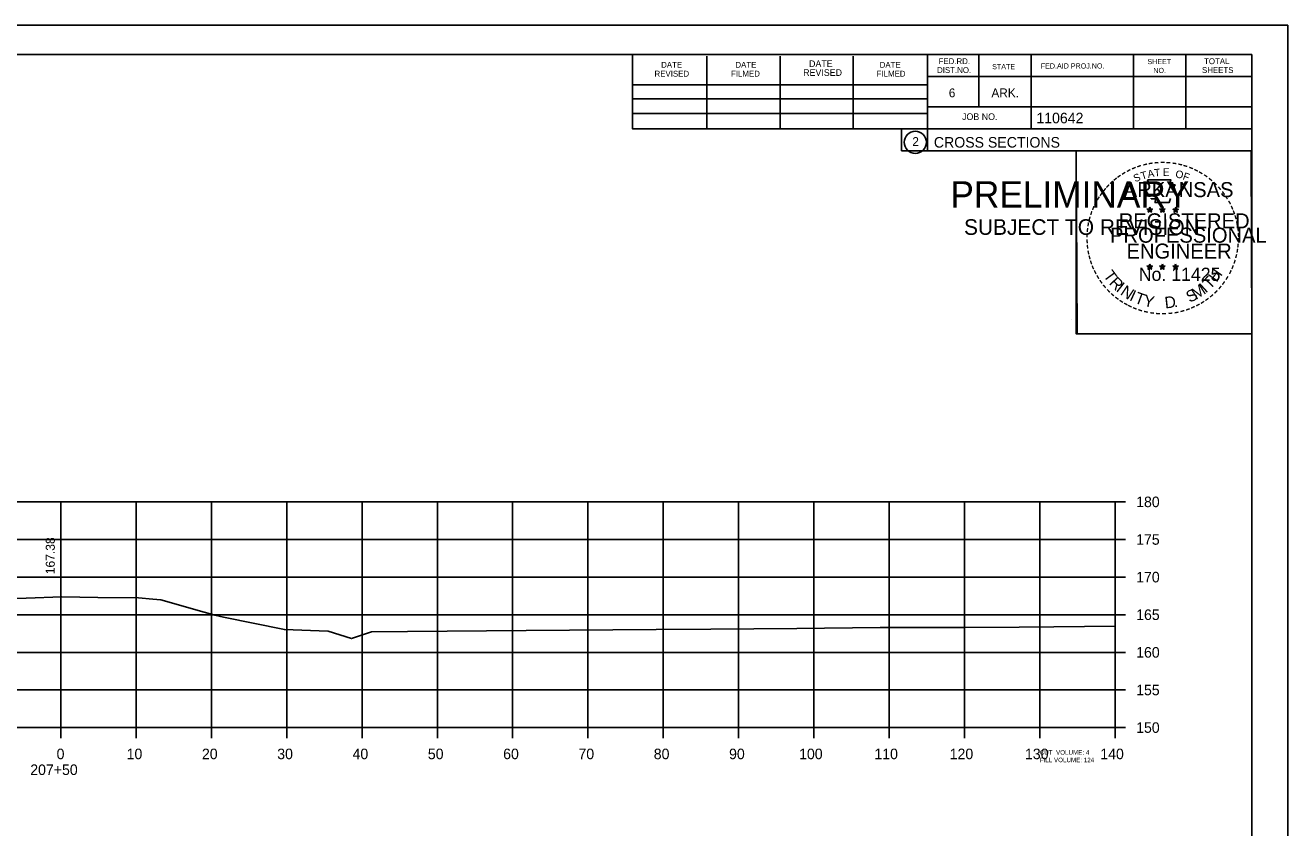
# Model space of a CAD drawing. Extents: x 1368503 to 1373085, y 379840 to 381833.
# Drawn here: x 1368668.3 to 1368836, y 380232.7 to 380339.4 of the extents above; entities that cross this region are included whole.
import ezdxf

# ---------------------------------------------------------------- set-up
doc = ezdxf.new("R2010")
doc.units = 0
for name, color, linetype in [('S_BRIDGE', 7, 'Continuous'), ('S_EDGE_PAVEMENT', 7, 'Continuous'), ('S_LANDSCAPING', 7, 'Continuous'), ('S_MISC_BOUNDARY', 7, 'Continuous'), ('S_MISC_BOUNDARY_ANNOT', 7, 'Continuous'), ('S_PHOTO_CENTERS', 7, 'Continuous'), ('S_PHOTO_NOTES', 7, 'Continuous'), ('S_TRAILS', 7, 'Continuous'), ('S_TRAILS_ANNOT', 7, 'Continuous')]:
    doc.layers.add(name, color=color, linetype=linetype)

msp = doc.modelspace()

# ---------------------------------------------------------------- linework, layer by layer
at = {"layer": 'S_BRIDGE'}
for p, q in [((1368515.06, 380335.49), (1368831.24, 380335.49)), ((1368748.98, 380325.61), (1368748.98, 380335.49)), ((1368758.84, 380325.61), (1368758.84, 380335.29)), ((1368768.6, 380325.61), (1368768.6, 380335.29)), ((1368778.28, 380325.61), (1368778.28, 380335.29)), ((1368788.14, 380335.49), (1368788.14, 380322.69)), ((1368794.98, 380335.49), (1368794.98, 380328.55)), ((1368801.92, 380335.49), (1368801.92, 380325.61)), ((1368815.5, 380335.49), (1368815.5, 380325.61)), ((1368822.44, 380335.49), (1368822.44, 380325.61)), ((1368831.24, 380130.03), (1368831.24, 380335.49)), ((1368748.98, 380331.47), (1368788.14, 380331.47)), ((1368831.24, 380332.55), (1368788.14, 380332.55)), ((1368831.24, 380332.57), (1368831.24, 380332.57)), ((1368748.98, 380329.61), (1368788.14, 380329.61)), ((1368831.24, 380328.55), (1368788.14, 380328.55)), ((1368791.1, 380328.55), (1368831.24, 380328.55)), ((1368748.98, 380325.61), (1368748.98, 380327.67)), ((1368748.98, 380327.67), (1368788.14, 380327.67)), ((1368831.24, 380325.61), (1368748.98, 380325.61)), ((1368788.14, 380322.69), (1368831.24, 380322.69))]:
    msp.add_line(p, q, dxfattribs=at)
msp.add_circle((1368786.53, 380323.82), 1.47, dxfattribs=at)
at = {"layer": 'S_EDGE_PAVEMENT'}
for p, q in [((1368813.06, 380246.03), (1368813.06, 380276.03)), ((1368814.46, 380276.03), (1368813.06, 380276.03)), ((1368814.46, 380271.03), (1368813.06, 380271.03)), ((1368814.46, 380266.03), (1368813.06, 380266.03)), ((1368814.46, 380261.03), (1368813.06, 380261.03)), ((1368814.46, 380256.03), (1368813.06, 380256.03)), ((1368814.46, 380251.03), (1368813.06, 380251.03)), ((1368533.06, 380246.03), (1368813.06, 380246.03)), ((1368673.06, 380244.63), (1368673.06, 380246.03)), ((1368683.06, 380244.63), (1368683.06, 380246.03)), ((1368693.06, 380244.63), (1368693.06, 380246.03)), ((1368703.06, 380244.63), (1368703.06, 380246.03)), ((1368713.06, 380244.63), (1368713.06, 380246.03)), ((1368723.06, 380244.63), (1368723.06, 380246.03)), ((1368733.06, 380244.63), (1368733.06, 380246.03)), ((1368743.06, 380244.63), (1368743.06, 380246.03)), ((1368753.06, 380244.63), (1368753.06, 380246.03)), ((1368763.06, 380244.63), (1368763.06, 380246.03)), ((1368773.06, 380244.63), (1368773.06, 380246.03)), ((1368783.06, 380244.63), (1368783.06, 380246.03)), ((1368793.06, 380244.63), (1368793.06, 380246.03)), ((1368803.06, 380244.63), (1368803.06, 380246.03)), ((1368813.06, 380244.63), (1368813.06, 380246.03)), ((1368814.46, 380246.03), (1368813.06, 380246.03))]:
    msp.add_line(p, q, dxfattribs=at)
at = {"layer": 'S_LANDSCAPING'}
for p, q in [((1368817.32, 380314.94), (1368817.67, 380314.83)), ((1368817.32, 380314.94), (1368817.58, 380314.9)), ((1368817.32, 380314.94), (1368817.56, 380314.82)), ((1368817.46, 380314.54), (1368817.67, 380314.83)), ((1368817.46, 380314.54), (1368817.58, 380314.78)), ((1368817.46, 380314.54), (1368817.67, 380314.75)), ((1368817.67, 380315.2), (1368817.63, 380314.95)), ((1368817.67, 380314.83), (1368817.67, 380315.2)), ((1368817.67, 380315.2), (1368817.72, 380314.95)), ((1368818.02, 380314.94), (1368817.67, 380314.83)), ((1368817.89, 380314.54), (1368817.67, 380314.83)), ((1368817.89, 380314.54), (1368817.67, 380314.75)), ((1368818.02, 380314.94), (1368817.73, 380314.89)), ((1368817.89, 380314.54), (1368817.75, 380314.83)), ((1368818.02, 380314.94), (1368817.82, 380314.84)), ((1368818.99, 380314.94), (1368819.34, 380314.83)), ((1368818.99, 380314.94), (1368819.25, 380314.9)), ((1368818.99, 380314.94), (1368819.23, 380314.82)), ((1368819.13, 380314.54), (1368819.34, 380314.83)), ((1368819.13, 380314.54), (1368819.25, 380314.78)), ((1368819.13, 380314.54), (1368819.34, 380314.75)), ((1368819.34, 380315.2), (1368819.3, 380314.95)), ((1368819.34, 380314.83), (1368819.34, 380315.2)), ((1368819.34, 380315.2), (1368819.39, 380314.95)), ((1368819.69, 380314.94), (1368819.34, 380314.83)), ((1368819.56, 380314.54), (1368819.34, 380314.83)), ((1368819.56, 380314.54), (1368819.34, 380314.75)), ((1368819.69, 380314.94), (1368819.4, 380314.89)), ((1368819.56, 380314.54), (1368819.42, 380314.83)), ((1368819.69, 380314.94), (1368819.49, 380314.84)), ((1368820.76, 380314.93), (1368821.11, 380314.82)), ((1368820.76, 380314.93), (1368821.01, 380314.89)), ((1368820.76, 380314.93), (1368820.99, 380314.81)), ((1368820.89, 380314.52), (1368821.11, 380314.82)), ((1368820.89, 380314.52), (1368821.02, 380314.77)), ((1368820.89, 380314.52), (1368821.1, 380314.74)), ((1368821.11, 380315.19), (1368821.07, 380314.93)), ((1368821.32, 380314.52), (1368821.1, 380314.74)), ((1368821.11, 380314.82), (1368821.11, 380315.19)), ((1368821.11, 380315.19), (1368821.16, 380314.94)), ((1368821.45, 380314.93), (1368821.11, 380314.82)), ((1368821.32, 380314.52), (1368821.11, 380314.82)), ((1368821.45, 380314.93), (1368821.17, 380314.88)), ((1368821.32, 380314.52), (1368821.18, 380314.81)), ((1368821.45, 380314.93), (1368821.25, 380314.83)), ((1368817.32, 380307.37), (1368817.67, 380307.26)), ((1368817.32, 380307.37), (1368817.57, 380307.33)), ((1368817.32, 380307.37), (1368817.56, 380307.25)), ((1368817.45, 380306.96), (1368817.67, 380307.26)), ((1368817.45, 380306.96), (1368817.58, 380307.21)), ((1368817.45, 380306.96), (1368817.67, 380307.18)), ((1368817.67, 380307.62), (1368817.63, 380307.37)), ((1368817.67, 380307.26), (1368817.67, 380307.62)), ((1368817.67, 380307.62), (1368817.72, 380307.37)), ((1368818.02, 380307.37), (1368817.67, 380307.26)), ((1368817.88, 380306.96), (1368817.67, 380307.26)), ((1368817.88, 380306.96), (1368817.67, 380307.18)), ((1368818.02, 380307.37), (1368817.73, 380307.32)), ((1368817.88, 380306.96), (1368817.74, 380307.25)), ((1368818.02, 380307.37), (1368817.81, 380307.27)), ((1368818.99, 380307.37), (1368819.34, 380307.26)), ((1368818.99, 380307.37), (1368819.24, 380307.33)), ((1368818.99, 380307.37), (1368819.23, 380307.25)), ((1368819.12, 380306.96), (1368819.34, 380307.26)), ((1368819.12, 380306.96), (1368819.25, 380307.21)), ((1368819.12, 380306.96), (1368819.34, 380307.18)), ((1368819.34, 380307.62), (1368819.3, 380307.37)), ((1368819.34, 380307.26), (1368819.34, 380307.62)), ((1368819.34, 380307.62), (1368819.39, 380307.37)), ((1368819.68, 380307.37), (1368819.34, 380307.26)), ((1368819.55, 380306.96), (1368819.34, 380307.26)), ((1368819.55, 380306.96), (1368819.34, 380307.18)), ((1368819.68, 380307.37), (1368819.4, 380307.32)), ((1368819.55, 380306.96), (1368819.41, 380307.25)), ((1368819.68, 380307.37), (1368819.48, 380307.27)), ((1368820.76, 380307.36), (1368821.1, 380307.25)), ((1368820.76, 380307.36), (1368821.01, 380307.32)), ((1368820.76, 380307.36), (1368820.99, 380307.24)), ((1368820.89, 380306.95), (1368821.1, 380307.25)), ((1368820.89, 380306.95), (1368821.01, 380307.2)), ((1368820.89, 380306.95), (1368821.1, 380307.17)), ((1368821.1, 380307.61), (1368821.06, 380307.36)), ((1368821.1, 380307.25), (1368821.1, 380307.61)), ((1368821.1, 380307.61), (1368821.15, 380307.36)), ((1368821.45, 380307.36), (1368821.1, 380307.25)), ((1368821.32, 380306.95), (1368821.1, 380307.25)), ((1368821.32, 380306.95), (1368821.1, 380307.17)), ((1368821.45, 380307.36), (1368821.17, 380307.31)), ((1368821.32, 380306.95), (1368821.18, 380307.24)), ((1368821.45, 380307.36), (1368821.25, 380307.26))]:
    msp.add_line(p, q, dxfattribs=at)
for points in [[(1368817.36, 380318.82), (1368817.63, 380317.99)], [(1368820.88, 380317.9), (1368821.02, 380318.18), (1368820.33, 380318.16), (1368820.48, 380318.82), (1368817.36, 380318.82)], [(1368817.86, 380316.4), (1368817.86, 380316.31), (1368818.42, 380316.29), (1368818.37, 380315.82), (1368820.24, 380315.82), (1368820.44, 380316.36)], [(1368817.67, 380315.2), (1368817.89, 380314.54), (1368817.32, 380314.94), (1368818.02, 380314.94), (1368817.46, 380314.54), (1368817.67, 380315.2)], [(1368819.34, 380315.2), (1368819.56, 380314.54), (1368818.99, 380314.94), (1368819.69, 380314.94), (1368819.13, 380314.54), (1368819.34, 380315.2)], [(1368821.11, 380315.19), (1368821.32, 380314.52), (1368820.76, 380314.93), (1368821.45, 380314.93), (1368820.89, 380314.52), (1368821.11, 380315.19)], [(1368817.67, 380307.62), (1368817.88, 380306.96), (1368817.32, 380307.37), (1368818.02, 380307.37), (1368817.45, 380306.96), (1368817.67, 380307.62)], [(1368819.34, 380307.62), (1368819.55, 380306.96), (1368818.99, 380307.37), (1368819.68, 380307.37), (1368819.12, 380306.96), (1368819.34, 380307.62)], [(1368821.1, 380307.61), (1368821.32, 380306.95), (1368820.76, 380307.36), (1368821.45, 380307.36), (1368820.89, 380306.95), (1368821.1, 380307.61)]]:
    msp.add_lwpolyline(points, dxfattribs=at)
for centre, radius in [((1368817.67, 380314.83), 0.172), ((1368817.67, 380314.83), 0.145), ((1368817.67, 380314.83), 0.116), ((1368817.67, 380314.83), 0.0991), ((1368817.67, 380314.83), 0.0747), ((1368817.67, 380314.83), 0.0495), ((1368817.67, 380314.83), 0.0296), ((1368819.34, 380314.83), 0.172), ((1368819.34, 380314.83), 0.145), ((1368819.34, 380314.83), 0.116), ((1368819.34, 380314.83), 0.0991), ((1368819.34, 380314.83), 0.0747), ((1368819.34, 380314.83), 0.0495), ((1368819.34, 380314.83), 0.0296), ((1368821.11, 380314.82), 0.172), ((1368821.11, 380314.82), 0.145), ((1368821.11, 380314.82), 0.116), ((1368821.11, 380314.82), 0.0991), ((1368821.11, 380314.82), 0.0747), ((1368821.11, 380314.82), 0.0495), ((1368821.11, 380314.82), 0.0296), ((1368817.67, 380307.26), 0.172), ((1368817.67, 380307.26), 0.145), ((1368817.67, 380307.26), 0.116), ((1368817.67, 380307.26), 0.0991), ((1368817.67, 380307.26), 0.0747), ((1368817.67, 380307.26), 0.0495), ((1368817.67, 380307.26), 0.0296), ((1368819.34, 380307.26), 0.172), ((1368819.34, 380307.26), 0.145), ((1368819.34, 380307.26), 0.116), ((1368819.34, 380307.26), 0.0991), ((1368819.34, 380307.26), 0.0747), ((1368819.34, 380307.26), 0.0495), ((1368819.34, 380307.26), 0.0296), ((1368821.1, 380307.25), 0.172), ((1368821.1, 380307.25), 0.145), ((1368821.1, 380307.25), 0.116), ((1368821.1, 380307.25), 0.0991), ((1368821.1, 380307.25), 0.0747), ((1368821.1, 380307.25), 0.0495), ((1368821.1, 380307.25), 0.0296)]:
    msp.add_circle(centre, radius, dxfattribs=at)
at = {"layer": 'S_MISC_BOUNDARY'}
msp.add_lwpolyline([(1368663, 380263.05), (1368668.44, 380263.25), (1368673.18, 380263.41), (1368677.97, 380263.33), (1368683.39, 380263.26), (1368685.3, 380263.1), (1368686.35, 380263.01), (1368692.08, 380261.39), (1368693.52, 380260.96), (1368694.68, 380260.7), (1368702.75, 380259.06), (1368708.52, 380258.86), (1368708.53, 380258.86), (1368708.54, 380258.86), (1368711.66, 380257.87), (1368713.77, 380258.56), (1368714.32, 380258.74), (1368719.09, 380258.79), (1368734.87, 380258.92), (1368752.13, 380259.08), (1368759.39, 380259.13), (1368770.78, 380259.22), (1368781.85, 380259.32), (1368786.11, 380259.32), (1368793.13, 380259.35), (1368800.34, 380259.39), (1368804.95, 380259.41), (1368813.06, 380259.49)], dxfattribs=at)
at = {"layer": 'S_PHOTO_CENTERS'}
for p, q in [((1368533.06, 380276.03), (1368813.06, 380276.03)), ((1368673.06, 380246.03), (1368673.06, 380276.03)), ((1368683.06, 380246.03), (1368683.06, 380276.03)), ((1368693.06, 380246.03), (1368693.06, 380276.03)), ((1368703.06, 380246.03), (1368703.06, 380276.03)), ((1368713.06, 380246.03), (1368713.06, 380276.03)), ((1368723.06, 380246.03), (1368723.06, 380276.03)), ((1368733.06, 380246.03), (1368733.06, 380276.03)), ((1368743.06, 380246.03), (1368743.06, 380276.03)), ((1368753.06, 380246.03), (1368753.06, 380276.03)), ((1368763.06, 380246.03), (1368763.06, 380276.03)), ((1368773.06, 380246.03), (1368773.06, 380276.03)), ((1368783.06, 380246.03), (1368783.06, 380276.03)), ((1368793.06, 380246.03), (1368793.06, 380276.03)), ((1368803.06, 380246.03), (1368803.06, 380276.03)), ((1368813.06, 380246.03), (1368813.06, 380276.03)), ((1368533.06, 380271.03), (1368813.06, 380271.03)), ((1368533.06, 380266.03), (1368813.06, 380266.03)), ((1368533.06, 380261.03), (1368813.06, 380261.03)), ((1368533.06, 380256.03), (1368813.06, 380256.03)), ((1368533.06, 380251.03), (1368813.06, 380251.03)), ((1368533.06, 380246.03), (1368813.06, 380246.03))]:
    msp.add_line(p, q, dxfattribs=at)
at = {"layer": 'S_PHOTO_NOTES'}
for p, q in [((1368502.66, 380339.38), (1368835.99, 380339.38)), ((1368807.27, 380300.23), (1368807.27, 380300.23))]:
    msp.add_line(p, q, dxfattribs=at)
for points in [[(1368502.65, 380339.38), (1368835.99, 380339.38), (1368835.99, 380126.05), (1368502.65, 380126.05)], [(1368748.98, 380335.49), (1368748.98, 380325.61), (1368784.71, 380325.61), (1368784.71, 380322.69), (1368807.91, 380322.69), (1368807.91, 380298.36), (1368831.24, 380298.36), (1368831.24, 380130.03), (1368515.06, 380130.03), (1368515.06, 380335.49)], [(1368807.91, 380322.69), (1368831.12, 380322.69), (1368831.24, 380298.36), (1368808.03, 380298.36)]]:
    msp.add_lwpolyline(points, close=True, dxfattribs=at)

# ---------------------------------------------------------------- texts
at = {"layer": 'S_BRIDGE'}
for s, height, p in [('DATE', 0.879, (1368772.42, 380333.83)), ('FED.RD.', 0.782, (1368789.62, 380334.21)), ('SHEET', 0.684, (1368817.36, 380334.21)), ('TOTAL', 0.782, (1368824.88, 380334.21)), ('REVISED', 0.782, (1368751.9, 380332.55)), ('DATE', 0.782, (1368752.78, 380333.73)), ('FILMED', 0.782, (1368762.06, 380332.55)), ('DATE', 0.782, (1368762.64, 380333.73)), ('REVISED', 0.879, (1368771.64, 380332.65)), ('FILMED', 0.782, (1368781.4, 380332.55)), ('DATE', 0.782, (1368781.8, 380333.73)), ('DIST.NO.', 0.782, (1368789.42, 380333.03)), ('STATE', 0.684, (1368796.74, 380333.53)), ('FED.AID PROJ.NO.', 0.684, (1368803.2, 380333.63)), ('NO.', 0.684, (1368818.14, 380333.03)), ('SHEETS', 0.782, (1368824.6, 380333.03)), ('6', 1.17, (1368790.98, 380329.81)), ('ARK.', 1.172, (1368796.64, 380329.81)), ('JOB NO.', 0.879, (1368792.74, 380326.79)), ('110642', 1.4, (1368802.61, 380326.35)), ('CROSS SECTIONS', 1.4, (1368789, 380323.12)), ('2', 1.17, (1368786.14, 380323.34))]:
    msp.add_text(s, height=height, rotation=360, dxfattribs=at).set_placement(p)
at = {"layer": 'S_LANDSCAPING'}
for s, height, rotation, p in [('-', 1.6, 5.8968, (1368818.27, 380320.46)), ('-', 1.6, 0.1862, (1368819.04, 380320.53)), ('-', 1.6, 357.743, (1368819.76, 380320.52)), ('-', 1.6, 36.2317, (1368813.67, 380318.6)), ('-', 1.6, 34.0636, (1368814.25, 380318.99)), ('-', 1.6, 28.7918, (1368814.85, 380319.36)), ('-', 1.6, 24.3072, (1368815.48, 380319.68)), ('S', 1, 21.594, (1368815.72, 380318.5)), ('-', 1.6, 19.1761, (1368816.11, 380319.95)), ('T', 1, 16.4036, (1368816.63, 380318.83)), ('-', 1.6, 13.6301, (1368816.86, 380320.19)), ('A', 1, 11.2132, (1368817.46, 380319.08)), ('-', 1.6, 10.2193, (1368817.54, 380320.35)), ('T', 1, 6.0228, (1368818.31, 380319.25)), ('E', 1, 0.8323, (1368819.41, 380319.36)), ('-', 1.6, 352.1617, (1368820.51, 380320.46)), ('O', 1, 350.4515, (1368821.02, 380319.15)), ('-', 1.6, 347.2049, (1368821.23, 380320.35)), ('F', 1, 340.0707, (1368821.97, 380318.92)), ('-', 1.6, 342.3362, (1368821.86, 380320.2)), ('-', 1.6, 337.8551, (1368822.6, 380319.97)), ('-', 1.6, 334.1211, (1368823.23, 380319.7)), ('-', 1.6, 329.6409, (1368823.81, 380319.42)), ('-', 1.6, 325.8627, (1368824.45, 380319.06)), ('-', 1.6, 48.423, (1368812.31, 380317.32)), ('-', 1.6, 42.9622, (1368812.76, 380317.8)), ('-', 1.6, 38.9507, (1368813.19, 380318.22)), ('ARKANSAS', 2, 360, (1368814.22, 380316.53)), ('-', 1.6, 320.5297, (1368825.06, 380318.63)), ('-', 1.6, 315.5786, (1368825.66, 380318.14)), ('-', 1.6, 309.8797, (1368826.23, 380317.59)), ('-', 1.6, 58.0706, (1368811.17, 380315.74)), ('-', 1.6, 54.2325, (1368811.5, 380316.27)), ('-', 1.6, 50.6142, (1368811.91, 380316.84)), ('-', 1.6, 306.6522, (1368826.75, 380316.99)), ('-', 1.4, 303.6753, (1368827.24, 380316.42)), ('-', 1.6, 72.3945, (1368810.38, 380313.89)), ('-', 1.6, 67.7743, (1368810.6, 380314.52)), ('-', 1.6, 62.8713, (1368810.86, 380315.13)), ('DWB', 0.01, 360, (1368817.66, 380314.83)), ('DWB', 0.01, 360, (1368819.33, 380314.83)), ('DWB', 0.01, 360, (1368821.09, 380314.82)), ('-', 1.6, 299.6684, (1368827.56, 380315.82)), ('-', 1.6, 294.6628, (1368827.88, 380315.2)), ('-', 1.6, 290.5728, (1368828.14, 380314.63)), ('-', 1.6, 81.2013, (1368810.05, 380312.46)), ('-', 1.6, 75.461, (1368810.18, 380313.18)), ('REGISTERED', 2, 360, (1368813.54, 380312.38)), ('-', 1.6, 285.1233, (1368828.37, 380314.05)), ('-', 1.6, 280.5493, (1368828.57, 380313.31)), ('-', 1.6, 89.0622, (1368809.95, 380311.07)), ('-', 1.6, 85.1863, (1368809.98, 380311.77)), ('PROFESSIONAL', 2, 360, (1368812.39, 380310.48)), ('-', 1.6, 276.5962, (1368828.74, 380312.54)), ('-', 1.6, 274.3301, (1368828.8, 380311.82)), ('-', 1.6, 94.1959, (1368809.99, 380310.35)), ('-', 1.6, 98.9479, (1368810.06, 380309.68)), ('ENGINEER', 2, 360, (1368814.58, 380308.36)), ('-', 1.6, 260.9953, (1368828.74, 380309.86)), ('-', 1.6, 263.5172, (1368828.81, 380310.52)), ('-', 1.6, 269.9407, (1368828.83, 380311.18)), ('-', 1.6, 101.7149, (1368810.19, 380308.95)), ('-', 1.6, 105.4578, (1368810.36, 380308.35)), ('-', 1.6, 109.0874, (1368810.57, 380307.72)), ('-', 1.6, 252.8681, (1368828.45, 380308.47)), ('-', 1.6, 255.7626, (1368828.63, 380309.19)), ('-', 1.6, 114.0643, (1368810.82, 380307.12)), ('-', 1.6, 115.7289, (1368811.13, 380306.51)), ('-', 1.6, 120.4471, (1368811.49, 380305.92)), ('T', 1.54, 306.0406, (1368811.43, 380306.1)), ('No. 11425', 1.757, 360, (1368816.21, 380305.4)), ('DWB', 0.01, 360, (1368817.66, 380307.25)), ('DWB', 0.01, 360, (1368819.33, 380307.25)), ('DWB', 0.01, 360, (1368821.09, 380307.24)), ('T', 1.54, 46.6444, (1368825.66, 380304.19)), ('H', 1.54, 54.6088, (1368826.55, 380305.13)), ('-', 1.6, 244.6197, (1368827.96, 380307.16)), ('-', 1.6, 247.8887, (1368828.23, 380307.79)), ('-', 1.6, 125.8934, (1368811.89, 380305.36)), ('-', 1.6, 130.7181, (1368812.35, 380304.81)), ('R', 1.54, 314.005, (1368812.19, 380305.05)), ('I', 1.54, 321.9694, (1368813.09, 380304.12)), ('N', 1.54, 326.5002, (1368813.66, 380303.65)), ('M', 1.54, 32.6563, (1368823.81, 380302.87)), ('I', 1.54, 42.1136, (1368825.1, 380303.71)), ('-', 1.6, 231.2538, (1368826.74, 380305.19)), ('-', 1.6, 233.8452, (1368827.17, 380305.76)), ('-', 1.6, 239.0712, (1368827.57, 380306.41)), ('-', 1.6, 134.2238, (1368812.87, 380304.26)), ('-', 1.6, 138.9338, (1368813.39, 380303.8)), ('-', 1.6, 144.6463, (1368813.95, 380303.39)), ('-', 1.6, 148.0898, (1368814.51, 380303.02)), ('I', 1.54, 335.3603, (1368814.87, 380302.86)), ('T', 1.54, 339.8912, (1368815.53, 380302.53)), ('Y', 1.54, 347.8556, (1368816.74, 380302.09)), ('D', 1.54, 6.3969, (1368819.73, 380301.73)), ('S', 1.54, 26.9312, (1368822.97, 380302.46)), ('-', 1.6, 212.2491, (1368824.65, 380303.26)), ('-', 1.6, 215.7363, (1368825.19, 380303.65)), ('-', 1.6, 221.0851, (1368825.74, 380304.12)), ('-', 1.6, 225.7653, (1368826.26, 380304.63)), ('-', 1.6, 151.5704, (1368815.09, 380302.7)), ('-', 1.6, 154.6002, (1368815.61, 380302.45)), ('-', 1.6, 158.5612, (1368816.24, 380302.19)), ('-', 1.6, 162.7983, (1368816.92, 380301.98)), ('-', 1.6, 167.5555, (1368817.64, 380301.82)), ('-', 1.6, 173.1155, (1368818.41, 380301.71)), ('-', 1.6, 176.5183, (1368819.16, 380301.65)), ('-', 1.6, 181.5918, (1368819.9, 380301.67)), ('-', 1.6, 185.8167, (1368820.71, 380301.75)), ('-', 1.6, 191.2858, (1368821.45, 380301.88)), ('.', 1.54, 13.7642, (1368820.92, 380301.86)), ('-', 1.6, 195.4743, (1368822.18, 380302.08)), ('-', 1.6, 200.7184, (1368822.85, 380302.32)), ('-', 1.6, 204.2516, (1368823.47, 380302.6)), ('-', 1.6, 207.3568, (1368824.1, 380302.91))]:
    msp.add_text(s, height=height, rotation=rotation, dxfattribs=at).set_placement(p)
at = {"layer": 'S_MISC_BOUNDARY_ANNOT'}
for s, height, p in [('PRELIMINARY', 3.5, (1368791.19, 380315.15)), ('DWB', 0.01, (1368791.94, 380317)), ('SUBJECT TO REVISION', 2.0751, (1368793, 380311.52))]:
    msp.add_text(s, height=height, rotation=360, dxfattribs=at).set_placement(p)
at = {"layer": 'S_TRAILS'}
for s, height, p in [('180', 1.4, (1368815.86, 380275.33)), ('175', 1.4, (1368815.86, 380270.33)), ('170', 1.4, (1368815.86, 380265.33)), ('165', 1.4, (1368815.86, 380260.33)), ('160', 1.4, (1368815.86, 380255.33)), ('155', 1.4, (1368815.86, 380250.33)), ('150', 1.4, (1368815.86, 380245.33)), ('0', 1.4, (1368672.5, 380241.83)), ('10', 1.4, (1368681.8, 380241.83)), ('20', 1.4, (1368691.8, 380241.83)), ('30', 1.4, (1368701.8, 380241.83)), ('40', 1.4, (1368711.8, 380241.83)), ('50', 1.4, (1368721.8, 380241.83)), ('60', 1.4, (1368731.8, 380241.83)), ('70', 1.4, (1368741.8, 380241.83)), ('80', 1.4, (1368751.8, 380241.83)), ('90', 1.4, (1368761.8, 380241.83)), ('100', 1.4, (1368771.1, 380241.83)), ('110', 1.4, (1368781.1, 380241.83)), ('120', 1.4, (1368791.1, 380241.83)), ('130', 1.4, (1368801.1, 380241.83)), ('CUT  VOLUME: 4', 0.6, (1368803.06, 380242.43)), ('140', 1.4, (1368811.1, 380241.83)), ('207+50', 1.4, (1368669, 380239.73)), ('FILL VOLUME: 124', 0.6, (1368803.06, 380241.43))]:
    msp.add_text(s, height=height, dxfattribs=at).set_placement(p)
at = {"layer": 'S_TRAILS_ANNOT'}
msp.add_text('167.38', height=1.2, rotation=90, dxfattribs=at).set_placement((1368672.26, 380266.41))

doc.saveas('drawing.dxf')
